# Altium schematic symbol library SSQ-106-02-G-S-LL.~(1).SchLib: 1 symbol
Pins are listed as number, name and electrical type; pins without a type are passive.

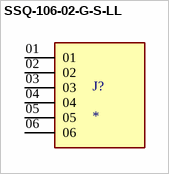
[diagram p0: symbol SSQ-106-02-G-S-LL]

## SSQ-106-02-G-S-LL
designator J?
Conn Socket Strip SKT 6 POS 2.54mm Solder ST Top Entry Thru-Hole Bulk; MF: Samtec; MP: SSQ-106-02-G-S-LL
footprint SAMTEC_SSQ-106-02-G-S-LL
pins: 01, 02, 03, 04, 05, 06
